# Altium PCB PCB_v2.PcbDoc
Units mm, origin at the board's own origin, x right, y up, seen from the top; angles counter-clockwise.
Board outline 180.34 x 98.04 mm, 2 copper layers (Top Layer, Bottom Layer); 31 components, 20 nets, 75 pads, 64 vias.
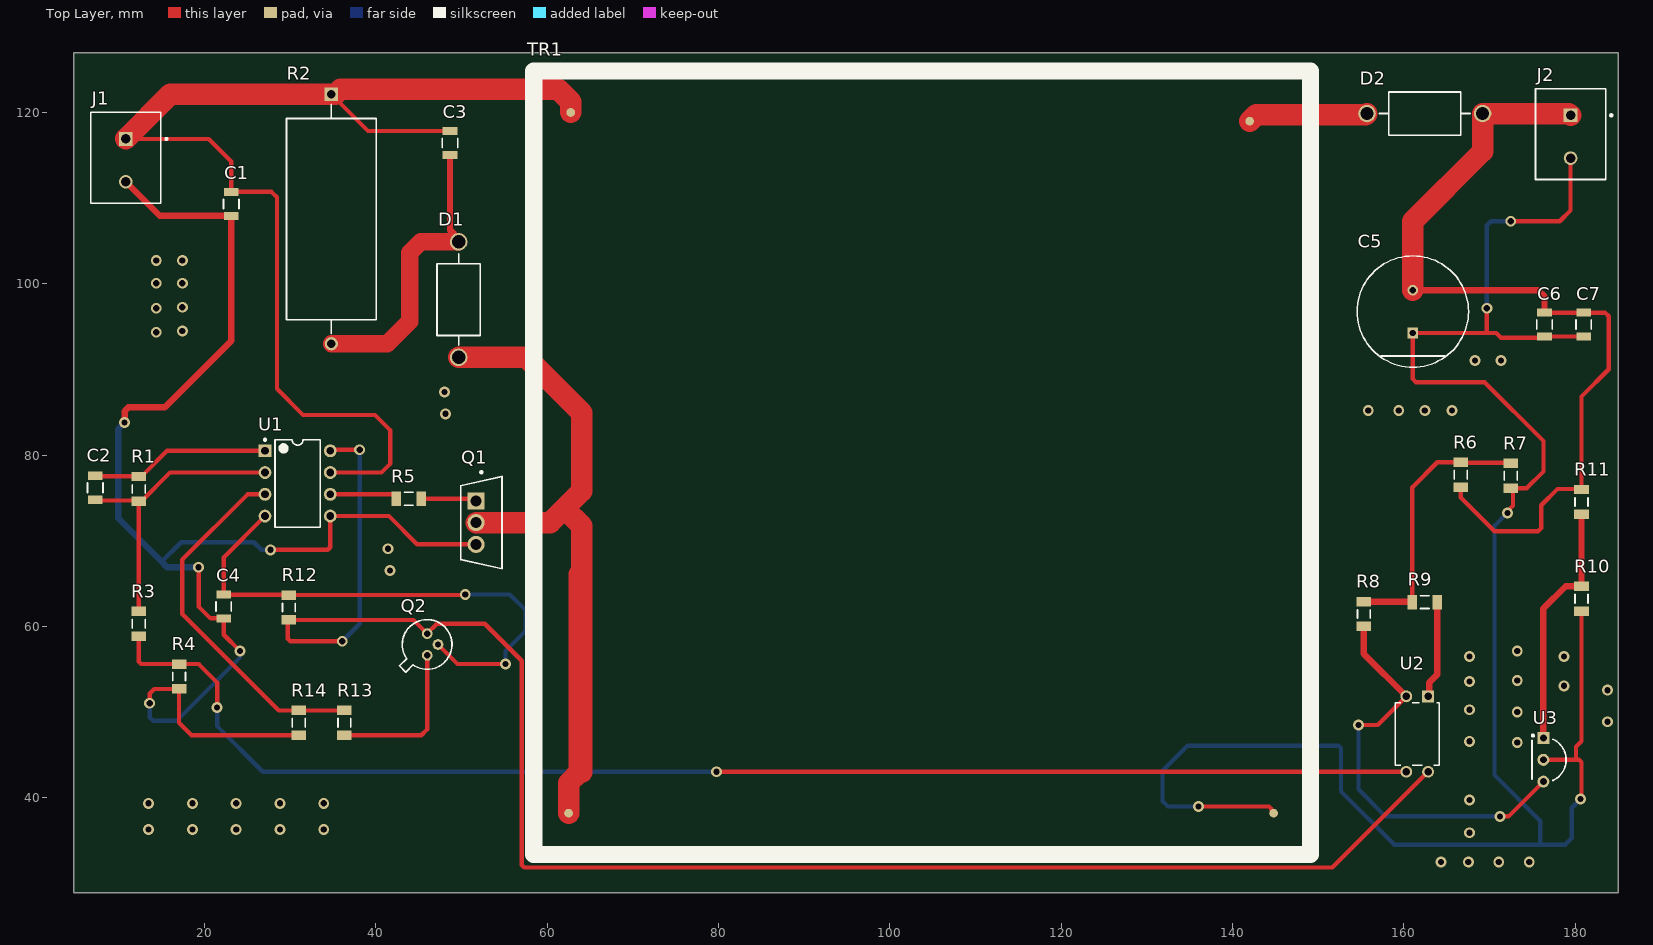
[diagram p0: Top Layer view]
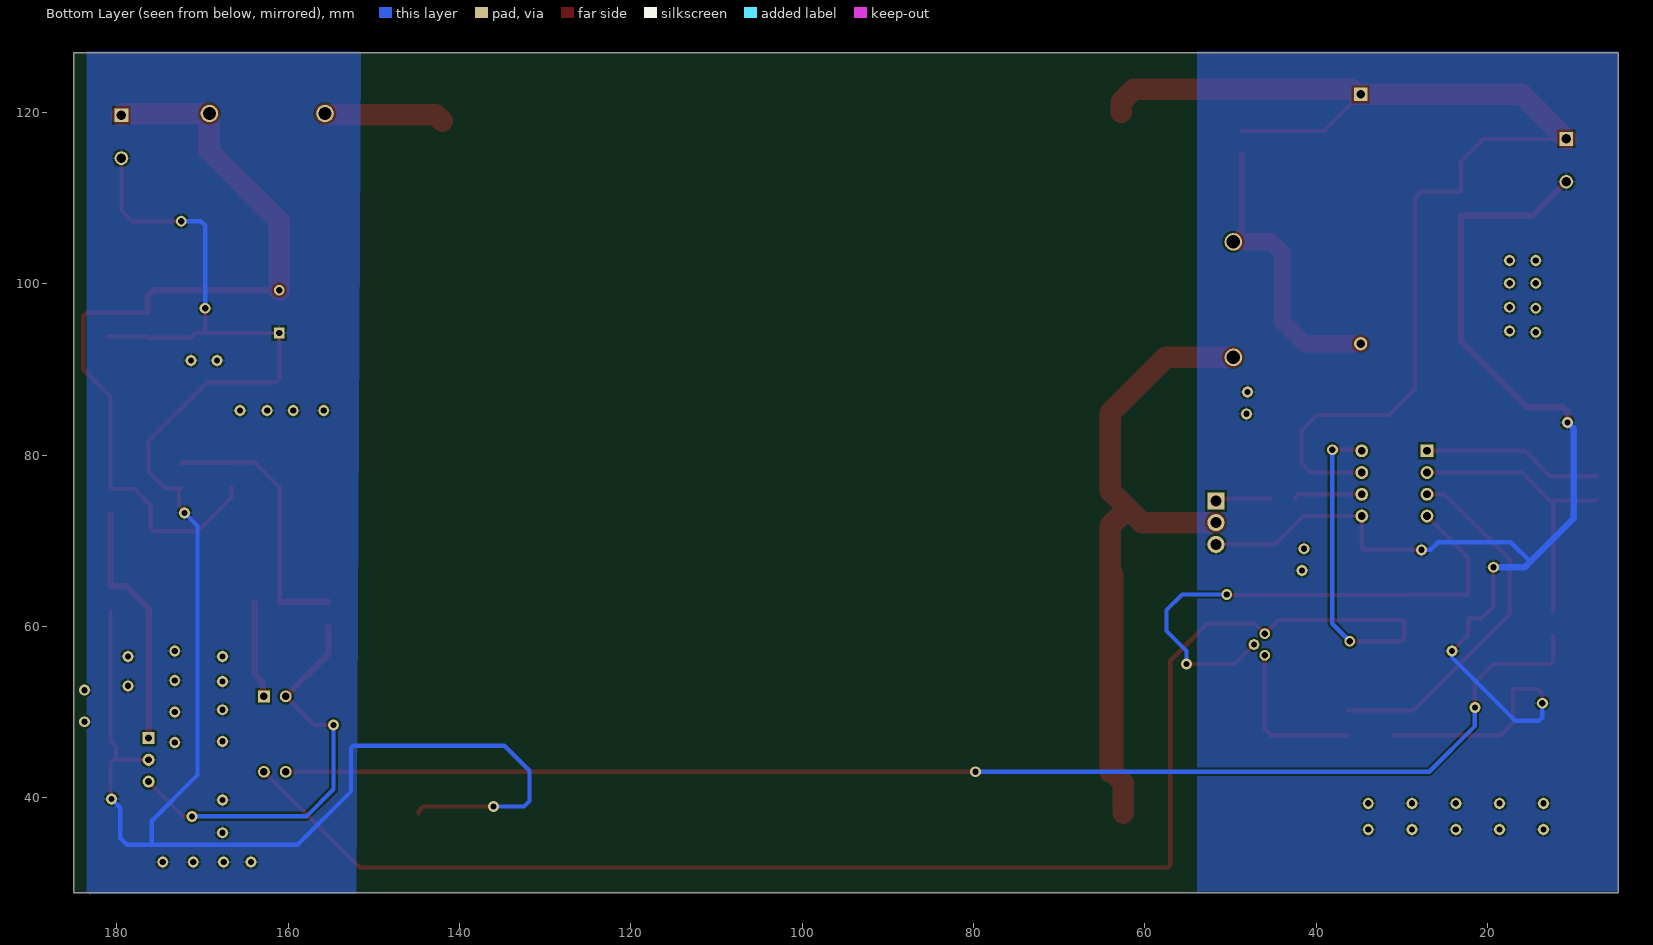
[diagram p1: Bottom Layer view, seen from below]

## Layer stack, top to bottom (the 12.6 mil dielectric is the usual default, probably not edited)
Top Solder: solder mask 0.0102, Solder Resist, Dk 3.5
Top Layer: signal copper 0.0356
Dielectric 1: dielectric 0.32, FR-4, Dk 4.8
Bottom Layer: signal copper 0.0356
Bottom Solder: solder mask 0.0102, Solder Resist, Dk 3.5

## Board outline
4.699,28.956 185.039,28.956 185.039,127 4.699,127

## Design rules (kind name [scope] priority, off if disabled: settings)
Clearance [All] p1: gap=0.254 ignorepadtopadclearanceinfootprint=FALSE except(0: Arc-Hole Track-Hole SMDPad-Hole THPad-Hole Via-Hole Fill-Hole Poly-Hole Region-Hole Text-Hole)
HoleSize [All] p1: absolutevalues=TRUE maxlimit=2.54 minlimit=0.05 maxpercent=80.000 minpercent=20.000
PolygonConnect [All] p1: connectstyle=Relief reliefconductorwidth=0.254 reliefentries=4 polygonreliefangle="90 Angle" airgapwidth=0.254
RoutingVias [All] p1: holewidth=0.711 width=1.27 viastyle="Through Hole" minholewidth=0.711 minwidth=1.27 maxholewidth=1.711 maxwidth=3.27
SolderMaskExpansion [All] p1: expansion=0.102 istentingtop=FALSE
Width [All] p1: maxlimit=6.254 minlimit=0.5 preferedwidth=0.5 minimp=50.000000 maximp=50.000000 favimp=50.000000
29 further rules are at their usual default settings.

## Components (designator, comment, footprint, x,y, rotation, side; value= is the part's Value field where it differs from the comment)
C1 "4.7uF (1206)" FP-C1206C-EB-MFG 23.114,109.347 r270 top value="1,000 pF"
C2 "1nF (1206)" FP-C1206C-EB-MFG 7.239,76.2 r90 top value="1,000 pF"
C3 "4.7uF (1206)" FP-C1206C-EB-MFG 48.641,116.459 r270 top value="1,000 pF"
C4 "1nF (1206)" FP-C1206C-EB-MFG 22.225,62.357 r270 top value="1,000 pF"
C5 "CAP 100uF UBX2A101MHL" FP-UBX2A101MHL-MFG 161.036,96.774 r90 top value=100uF
C6 "20uF (1206)" FP-C1206C-EB-MFG 176.403,95.25 r90 top value="1,000 pF"
C7 "1nF (1206)" FP-C1206C-EB-MFG 180.975,95.25 r90 top value="1,000 pF"
D1 "Schottky (MBR3100RLG)" ONSC-AXIAL_LEAD-2-267-05_V 49.657,98.171 r270 top
D2 "MUR460" ONSC-AXIAL_LEAD-2-267-05_V 162.433,119.888 r180 top
J1 "282836-2" TECO-282836-2_V 10.795,114.427 r270 top
J2 "282836-2" TECO-282836-2_V 179.451,117.181 r270 top
Q1 "IRFI540N (TO-220)" FP-PG-TO220-3-MFG 52.299,72.136 r0 top
Q2 "2N2222A (TO18-3)" STM-TO-18-3 45.974,57.912 r90 top
R1 "10k Ohm (1206)" RESC3216X60X45NL10T20 12.319,76.073 r270 top
R2 "5W (300-1k Ohm)" FP-SQP500-MFG 34.798,107.569 r270 top value=1.2Ω
R3 "4.99k Ohm (1206)" RESC3216X60X45NL10T20 12.319,60.325 r90 top
R4 "7.68k Ohm (1206)" RESC3216X60X45NL10T20 17.018,54.176 r90 top
R5 "8 Ohm (1206)" RESC3216X60X45NL10T20 43.815,74.93 r180 top
R6 "6k Ohm (1206)" RESC3216X60X45NL10T20 166.624,77.724 r90 top
R7 "3k Ohm (1206)" RESC3216X60X45NL10T20 172.466,77.597 r270 top
R8 "13.7k Ohm (1206)" RESC3216X60X45NL10T20 155.321,61.468 r270 top
R9 "15.4k Ohm (1206)" RESC3216X60X45NL10T20 162.433,62.865 r0 top
R10 "3.01k Ohm (1206)" RESC3216X60X45NL10T20 180.721,63.246 r270 top
R11 "54.9k Ohm (1206)" RESC3216X60X45NL10T20 180.721,74.549 r270 top
R12 "8.66k Ohm (1206)" RESC3216X60X45NL10T20 29.845,62.23 r90 top
R13 "2.7k Ohm (1206)" RESC3216X60X45NL10T20 36.322,48.768 r90 top
R14 "1k Ohm (1206)" RESC3216X60X45NL10T20 30.988,48.768 r90 top
TR1 "transformer" Transformer_flyback 62.738,37.973 r0 top
U1 "UC3845N" P0008A 30.861,76.708 r0 top
U2 "PC817A / VO618A-2 (DIP4)" DIP-4_VO618A_VIS 162.814,51.853 r270 top
U3 "TL431ILP (TO92-3)" LP0003A 176.276,44.45 r0 top

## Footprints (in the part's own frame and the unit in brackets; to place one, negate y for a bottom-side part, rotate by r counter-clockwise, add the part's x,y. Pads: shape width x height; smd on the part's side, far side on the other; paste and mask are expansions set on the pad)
DIP-4_VO618A_VIS [mil]
  rect 54x54 / inner round 60 / far side rect 54x54 hole 34 paste-27 mask+0: 1(0,0)
  round 54 / inner round 60 / far side round 54 hole 34 paste-27 mask+0: 2(0,-100) 3(346.46,-100) 4(346.46,0)
  silkscreen extent 30,-151 316,51, body extent -5,-146 361,46, height 174
FP-C1206C-EB-MFG [mm]
  rect 0.95x1.7 smd paste+0 mask+0: 1(-1.4,0) 2(1.4,0)
  silkscreen extent -0.55,-0.9 0.55,0.9, body extent -2,-1 2,1, height 0.25
FP-PG-TO220-3-MFG [mm]
  rect 2x2 hole 1.3 paste-1000 mask+0: 1(-0.61,2.54)
  round 2 hole 1.3 paste-1000 mask+0: 2(-0.61,0) 3(-0.61,-2.54)
  silkscreen extent -2.41,-5.38 2.41,6, body extent -2.51,-5.6 2.51,5.6, height 0.25
FP-SQP500-MFG [mm]
  rect 1.55x1.55 hole 1 paste-1000 mask+0: 1(-14.555,0)
  round 1.55 hole 1 paste-1000 mask+0: 2(14.555,0)
  silkscreen extent -13.38,-5.25 13.38,5.25, body extent -15.43,-5.35 15.43,5.35, height 0.25
FP-UBX2A101MHL-MFG [mm]
  rect 1.25x1.25 hole 0.75 paste-1000 mask+0: 1(-2.5,0)
  round 1.25 hole 0.75 paste-1000 mask+0: 2(2.5,0)
  silkscreen extent -6.5,-6.5 6.5,6.5, body extent -6.6,-6.6 6.6,6.6, height 0.25
LP0003A [mm] "TO, Flat Index; 3 In-Line, Formed Axial Leads; Body Dia. 4.8mm; Leads 0.56 x 0.41 mm (max)"
  rrect7% 1.4x1.4 hole 0.8: 1(0,2.54)
  round 1.4 hole 0.8: 2(0,0) 3(0,-2.54)
  silkscreen extent -1.35,-2.41 2.65,2.95, body extent -1.33,-2.83 2.35,2.83, height 9.01
ONSC-AXIAL_LEAD-2-267-05_V [mm] "AXIAL, 2-Leads, Diameter 5.05mm"
  round 2.05 hole 1.55: 1(-6.745,0) 2(6.745,0)
  silkscreen extent -5.32,-2.52 5.32,2.52
P0008A [mm] "DIP, 8-Leads, Body 10.15x6.6mm, Pitch 2.54mm"
  rect 1.5x1.5 hole 0.9: 1(-3.81,3.81)
  round 1.5 hole 0.9: 2(-3.81,1.27) 3(-3.81,-1.27) 4(-3.81,-3.81) 5(3.81,-3.81) 6(3.81,-1.27) 7(3.81,1.27) 8(3.81,3.81)
  silkscreen extent -3.93,-5.1 2.65,5.23, body extent -3.95,-5.07 3.95,5.07, height 5.08
RESC3216X60X45NL10T20 [mm] "Chip Resistor, 2-Leads, Body 3.20x1.60mm, IPC Medium Density"
  rect 1.1x1.7 smd: 1(-1.45,0) 2(1.45,0)
  silkscreen extent -0.5,-0.75 0.5,0.75, body extent -1.65,-0.85 1.65,0.85, height 0.6
STM-TO-18-3 [mm] "TO, 3-Leads, Diameter 5.8mm"
  round 1.25 hole 0.75: 1(0,-1.27) 2(1.27,0) 3(-1.27,0)
  silkscreen extent -3.23,-2.9 2.9,3.23, body extent -3.23,-2.9 2.9,3.23, height 5.3
TECO-282836-2_V [mm] "Female Header, Pitch 5mm, 1 x 2 Position, Height 10mm"
  rect 1.6x1.6 hole 1.1: 1(-2.5,0)
  round 1.6 hole 1.1: 2(2.5,0)
  silkscreen extent -5.6,-4.1 5,4.88, body extent -5.6,-4.1 5,4.1, height 10
Transformer_flyback [mil]
  round 40 smd mask+100: 1(0,3230) 2(-10,10) 3(3120,3190) 4(3230,10)
  silkscreen extent -170,-180 3400,3420

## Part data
C1 C2 C3 C4 C6 C7: library part CMP-03020-000955-1, "Multilayer Ceramic Capacitor, C Series, 1000 Pf, - 5%, C0g / Np0, 100 V, 1206 [3216 Metric] Rohs Compliant: Yes", Capacitance="1,000 pF", Manufacturer=KEMET, Manufacturer Part Number=C1206C102J1GACTU, Package=C1206C-EB, Temperature="-55°C to +150°C", Temperature Characteristic=C0G, Temperature Coefficient=15%, Temperature Range High=+150°C, Temperature Range Low=-55°C, Tolerance=0.05, Voltage Rating="100 V"
C5: library part CMP-12462-000004-1, "CAP ALUM 100UF 20% 100V RADIAL", Capacitance=100uF, Leakage Current=300uA, Manufacturer=Nichicon, Manufacturer Part Number=UBX2A101MHL, Package=0, Ripple Current=950mA, Temperature="-55°C to +150°C", Temperature Range High=+150°C, Temperature Range Low=-55°C, Tolerance=20%, Voltage Rating=100V
D1: library part CMP-1055-00020-1, "Rectifier, 2-Pin Axial_Lead, Pb-Free, Tape and Reel", Manufacturer="On Semiconductor", PartNumber=MBR3100RLG
D2: library part CMP-0902-00067-1, "SWITCHMODE(TM) Power Rectifier, 2-Pin Axial_Lead, Pb-Free, Bulk Bag", Manufacturer="On Semiconductor"
J1 J2: library part CMP-1684-00017-1, "Female Header, Pitch 5 mm, 1 x 2 Position, Height 10 mm, Tail Length 3.5 mm, Rohs, Bulk", Color=Green, Current=13.5A, Manufacturer="TE Connectivity", Package Description="Female Header, Pitch 5 mm, 1 x 2 Position, Height 10 mm, Tail Length 3.5 mm", Package Reference=THD, Standard Package=300, Voltage=300V
Q1: library part CMP-32901-000575-1, "MOSFET N-CH 100V 20A TO220FP", Case/Package=TO-220-3, Continuous Drain Current (ID)=20A, Drain to Source Breakdown Voltage=100V, Drain to Source Resistance=52mR, Gate to Source Voltage (Vgs)=20V, Max Operating Temperature=175°C, Max Power Dissipation=54W, Min Operating Temperature=-55°C, Threshold Voltage=4V, Input Capacitance=1.4nF
Q2: library part CMP-2000-05381-1, "High Speed Switch, 0.6 A IC, -65 to 175 degC, 3-Pin TO-18, RoHS, Bulk", Collector Emitter Voltage V(br)ceo=40V, DC Collector Current=600mA, DC Current Gain hFE=300hFE, Manufacturer=STMicroelectronics, Operating Temperature Max=175degC, Package Description="3-Pin Through Hole Device, Dia 5.8 mm, Pitch 1.27 mm", Package Reference=TO-18-3, Power Dissipation Pd=500mW, Transistor Case Style=TO-18, Transition Frequency ft=300MHz
R1 R3 R4 R5 R6 R7 R8 R9 R10 R11 R12 R13 R14: library part CMP-2003-02424-1, Manufacturer="Vishay Dale", Part Number=CRCW12068R25FKEA
R2: library part CMP-03413-000003-1, Manufacturer=Yageo, Manufacturer Part Number=SQP500JB-1R2, Package=SQP500, Power Rating=5W, Resistance=1.2Ω, Temperature="-55°C to +155°C", Temperature Coefficient=300ppm/°C, Temperature Range High=+155°C, Temperature Range Low=-55°C, Tolerance=5%, Voltage Rating=350V
U1: library part CMP-0319-00305-2, "PWM Controller with Current Control, 50 % Duty Cycle, 0 to +70 degC, 8-pin PDIP (P), Green (RoHS & no Sb/Br)", Frequency(Max)(kHz)=450, Manufacturer="Texas Instruments", Rating=Catalog
U2: library part CMP-00030-24929081_03-1, "VO618A-2 Optocoupler DC-IN 1-CH Transistor DC-OUT 4-Pin PDIP", Case/Package=DIP, Collector Emitter Saturation Voltage=400mV, Collector Emitter Voltage (VCEO)=80V, Current Transfer Ratio=125%, Forward Current=60mA, Forward Voltage=1.1V, Max Collector Current=50mA, Max Operating Temperature=110°C, Max Power Dissipation=150mW, Min Operating Temperature=-55°C, Reverse Breakdown Voltage=6V, Isolation Voltage=5.3kV
U3: library part CMP-0366-00043-2, "Adjustable Precision Shunt Regulator, 34 ppm / degC, 100 mA, -40 to 85 degC, 3-pin TO-92 (LP), Pb-Free (RoHS)", Manufacturer="Texas Instruments", PartNumber=TL431ILP, Rating=Military, Temp Coeff(Max)(ppm/ degree C)=92, Temp Coeff(Typ)(ppm/ degree C)=34

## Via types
v1: diameter 1.27, hole 0.72, Top Layer to Bottom Layer, 46 vias
v2: diameter 1.27/1.27 (per signal layer), hole 0.72, Top Layer to Bottom Layer, 18 vias

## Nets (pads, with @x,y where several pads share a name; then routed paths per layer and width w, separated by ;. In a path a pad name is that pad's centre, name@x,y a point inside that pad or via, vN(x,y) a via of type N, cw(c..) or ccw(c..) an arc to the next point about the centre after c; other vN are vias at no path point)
GND: C1.2 C4.2 J1.2 Q1.3 R4.1 R14.1 U1.5 | length 164.3
  Top Layer w0.5: v2(13.589,51.054) 13.589,52.197 14.118,52.726 R4.1 17.018,48.768 18.468,47.318 R14.1 ; v2(19.304,66.929) 19.304,62.357 20.701,60.96 22.222,60.96 C4.2 22.225,59.055 v2(24.13,57.15) ; v2(27.686,68.961) 34.378,68.961 34.671,69.254 U1.5 41.529,72.898 44.831,69.596 Q1.3
  Top Layer w0.75: v2(10.668,83.82) 10.668,85.159 11.107,85.598 15.367,85.598 23.114,93.345 C1.2 14.775,107.947 J1.2
  Bottom Layer w0.5: v2(13.589,51.054) 13.589,49.403 13.97,49.022 16.764,49.022 24.13,56.388 v2(24.13,57.15) ; 14.986,67.564 17.272,69.85 25.738,69.85 26.627,68.961 v2(27.686,68.961)
  Bottom Layer w0.75: v2(10.668,83.82) 9.906,83.058 9.906,72.644 14.986,67.564 15.621,66.929 v2(19.304,66.929)
  other v1: 13.462,36.322 18.574,36.322 23.685,36.322 28.797,36.322 33.909,36.322 13.462,39.37 18.574,39.37 23.685,39.37 28.797,39.37 33.909,39.37 41.656,66.548 41.402,69.088 48.133,84.836 48.006,87.376 14.351,94.361 17.399,94.488 14.351,97.155 17.399,97.282 14.351,100.076 17.399,100.076 14.351,102.743 17.399,102.743
NetC1_1: C1.1 C3.1 J1.1 R2.1 TR1.1 U1.7 | length 143.3
  Top Layer w0.5: J1.1 20.487,116.927 23.114,114.3 C1.1 27.81,110.747 28.448,110.109 28.448,87.757 31.496,84.709 39.878,84.709 41.656,82.931 41.656,78.994 40.64,77.978 U1.7 ; R2.1 39.063,117.859 C3.1
  Top Layer w2.5: J1.1 15.992,122.124 R2.1 35.252,122.124 35.86,122.732 61.274,122.732 62.738,121.268 TR1.1
NetC2_1: C2.1 R1.2 R3.2 U1.2 | length 34.1
  Top Layer w0.5: C2.1 7.327,74.712 12.23,74.712 R1.2 ; R3.2 R1.2 ; U1.2 15.974,77.978 12.619,74.623 R1.2
NetC2_2: C2.2 R1.1 U1.1 | length 21.1
  Top Layer w0.5: C2.2 7.278,77.561 12.281,77.561 R1.1 12.619,77.523 15.614,80.518 U1.1
NetC3_2: C3.2 D1.1 R2.2 | length 35
  Top Layer w0.75: C3.2 48.641,106.284 49.657,105.268 D1.1
  Top Layer w2: R2.2 41.325,93.014 43.942,95.631 43.942,103.632 45.226,104.916 D1.1
NetC4_1: C4.1 Q2.1 R12.2 U1.4 | length 63.3
  Top Layer w0.5: U1.4 22.225,68.072 C4.1 22.263,63.719 29.806,63.719 R12.2 50.345,63.68 v2(50.419,63.754) ; Q2.1 49.53,55.626 v2(55.118,55.626)
  Bottom Layer w0.5: v2(50.419,63.754) 55.626,63.754 57.451,61.929 57.451,59.483 55.118,57.15 v2(55.118,55.626)
NetC5_2: C5.2 C6.2 C7.2 D2.1 J2.1 R6.1 R11.1 | length 101.7
  Top Layer w0.5: R6.1 166.624,75.057 170.561,71.12 175.641,71.12 176.022,71.501 176.022,74.168 177.927,76.073 180.647,76.073 R11.1 180.721,86.868 183.896,90.043 183.896,96.227 183.473,96.65 C7.2 C6.2
  Top Layer w0.75: C5.2 175.681,99.274 176.403,98.552 C6.2
  Top Layer w2.5: C5.2 161.036,107.315 169.178,115.457 D2.1 179.244,119.888 J2.1
NetD1_2: D1.2 Q1.2 TR1.2 | length 100.1
  Top Layer w2.5: D1.2 57.545,91.426 64.008,84.963 64.008,75.819 61.976,73.787 ; Q1.2 60.325,72.136 61.976,73.787 ; TR1.2 62.484,41.744 63.728,42.988 63.728,66.105 ; 64.008,42.988 64.008,71.755 61.976,73.787
NetD2_2: D2.2 TR1.3 | length 14.1
  Top Layer w2.5: TR1.3 142.748,119.761 155.561,119.761 D2.2
NetQ1_1: Q1.1 R5.1 | length 6.5
  Top Layer w0.5: R5.1 51.435,74.93 Q1.1
NetQ2_2: Q2.2 R12.1 U1.8 U2.4 | length 199.9
  Top Layer w0.5: U1.8 34.798,80.645 v2(38.1,80.645) ; v2(36.068,58.293) 30.011,58.293 29.718,58.586 29.718,60.653 R12.1 44.376,60.78 Q2.2 47.117,60.325 52.705,60.325 57.023,56.007 57.023,32.17 57.316,31.877 151.638,31.877 U2.4
  Bottom Layer w0.5: v2(36.068,58.293) 38.1,60.325 v2(38.1,80.645)
NetQ2_3: Q2.3 R13.1 | length 18.6
  Top Layer w0.5: R13.1 45.286,47.318 45.974,48.006 Q2.3
NetR3_1: R3.1 R4.2 U2.3 | length 159.3
  Top Layer w0.5: R3.1 12.319,55.919 12.612,55.626 R4.2 19.304,55.626 21.463,53.467 v2(21.463,50.546) ; v2(79.756,43.053) 160.02,43.053 160.147,42.926 U2.3
  Bottom Layer w0.5: v2(21.463,50.546) 21.463,48.387 26.797,43.053 v2(79.756,43.053)
NetR5_2: R5.2 U1.6 | length 8
  Top Layer w0.5: U1.6 42.065,75.438 42.365,75.138 R5.2
NetR6_2: R6.2 R7.1 R8.1 R9.1 | length 31.8
  Top Layer w0.5: R9.1 160.983,76.274 163.883,79.174 R6.2 166.688,79.11 172.403,79.11 R7.1
  Top Layer w0.75: R8.1 155.347,62.891 160.957,62.891 R9.1
NetR8_2: R8.2 U2.2 U3.3 | length 49.3
  Top Layer w0.5: v2(154.686,48.514) 156.935,48.514 U2.2 ; v2(171.196,37.846) 172.212,37.846 U3.3
  Top Layer w0.75: R8.2 155.321,56.806 U2.2
  Bottom Layer w0.5: v2(154.686,48.514) 154.686,41.021 157.861,37.846 v2(171.196,37.846)
NetR9_2: R9.2 U2.1 | length 11.5
  Top Layer w0.75: U2.1 162.941,51.98 162.941,53.467 163.883,54.409 R9.2
NetR10_1: R10.1 R11.2 U3.1 | length 29
  Top Layer w0.75: U3.1 176.276,62.103 178.869,64.696 R10.1 R11.2
NetR13_2: R13.2 R14.2 U1.3 | length 42.7
  Top Layer w0.5: U1.3 25.019,75.438 17.399,67.818 17.399,61.468 28.649,50.218 R14.2 R13.2
SGND: C5.1 C6.1 C7.1 J2.2 R7.2 R10.2 TR1.4 U3.2 | length 231.7
  Top Layer w0.5: v2(136.017,38.989) 144.257,38.989 144.522,38.724 144.522,38.625 144.78,38.367 TR1.4 ; v2(169.672,97.155) 169.672,94.274 ; v2(172.085,73.279) 172.085,73.487 172.72,74.122 172.72,75.893 R7.2 174.318,76.147 176.276,78.105 176.276,81.661 169.418,88.519 161.417,88.519 161.036,88.9 C5.1 169.672,94.274 ; v2(172.466,107.315) 178.181,107.315 179.451,108.585 J2.2 ; U3.2 180.086,44.45 ; v2(180.594,39.878) 180.721,40.005 180.721,44.157 180.428,44.45 180.086,44.45 ; R10.2 180.721,46.609 180.086,45.974 180.086,44.45 ; C7.1 C6.1 176.279,93.726 171.323,93.726 170.775,94.274 169.672,94.274
  Bottom Layer w0.5: v2(136.017,38.989) 132.461,38.989 131.826,39.624 131.826,43.18 134.747,46.101 152.361,46.101 152.654,45.808 152.654,40.767 158.877,34.544 175.895,34.544 ; v2(169.672,97.155) 169.672,106.807 170.18,107.315 v2(172.466,107.315) ; v2(172.085,73.279) 170.561,71.755 170.561,42.672 175.895,37.338 175.895,34.544 ; v2(180.594,39.878) 179.578,38.862 179.578,35.306 178.816,34.544 175.895,34.544
  other v1: 164.338,32.512 167.513,32.512 171.069,32.512 174.625,32.512 167.64,35.941 167.64,39.751 173.228,46.482 167.64,46.609 183.769,48.895 173.228,50.038 167.64,50.292 183.769,52.578 178.689,53.086 167.64,53.594 173.228,53.721 167.64,56.515 178.689,56.515 173.228,57.15 155.829,85.217 159.385,85.217 162.433,85.217 165.608,85.217 168.275,91.059 171.323,91.059

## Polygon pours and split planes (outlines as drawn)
SGND on Bottom Layer "SGND_L02_P001" (solid, pour order 1): 151.511,127 151.638,127.127 183.515,127.127 183.515,29.083 183.134,28.702 183.007,28.829 152.019,28.829
GND on Bottom Layer "GND_L02_P000" (solid, pour order 0): 4.699,127 4.826,127.127 53.848,127.127 53.848,29.083 53.721,28.956 53.594,29.083 4.699,29.083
